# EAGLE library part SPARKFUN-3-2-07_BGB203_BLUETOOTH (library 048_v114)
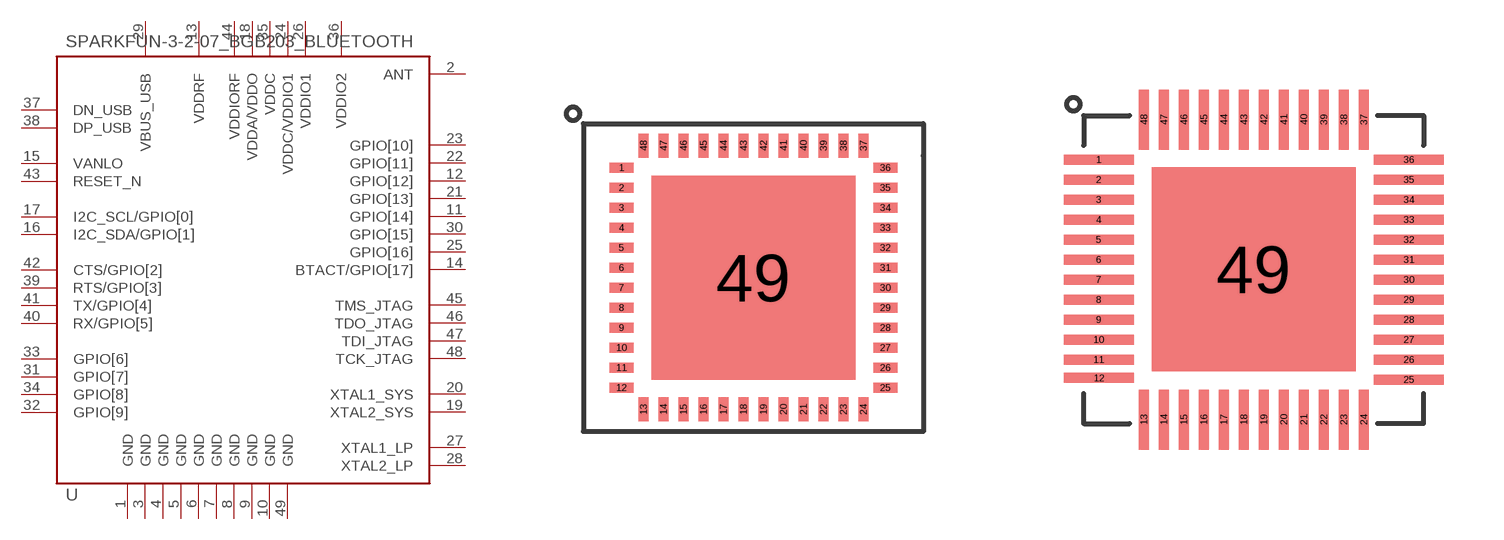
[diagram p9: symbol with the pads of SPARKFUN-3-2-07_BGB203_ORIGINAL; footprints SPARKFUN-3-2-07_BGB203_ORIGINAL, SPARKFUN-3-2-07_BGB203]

Designator prefix -

## SPARKFUN-3-2-07_BGB203_BLUETOOTHOLD  [SPARKFUN-3-2-07_BGB203_ORIGINAL]
1  GND
2  ANT
3  GND
4  GND
5  GND
6  GND
7  GND
8  GND
9  GND
10  GND
11  GPIO[14]
12  GPIO[12]
13  VDDRF
14  BTACT/GPIO[17]
15  VANLO
16  I2C_SDA/GPIO[1]
17  I2C_SCL/GPIO[0]
18  VDDA/VDDO
19  XTAL2_SYS
20  XTAL1_SYS
21  GPIO[13]
22  GPIO[11]
23  GPIO[10]
24  VDDC/VDDIO1
25  GPIO[16]
26  VDDIO1
27  XTAL1_LP
28  XTAL2_LP
29  VBUS_USB
30  GPIO[15]
31  GPIO[7]
32  GPIO[9]
33  GPIO[6]
34  GPIO[8]
35  VDDC
36  VDDIO2
37  DN_USB
38  DP_USB
39  RTS/GPIO[3]
40  RX/GPIO[5]
41  TX/GPIO[4]
42  CTS/GPIO[2]
43  RESET_N
44  VDDIORF
45  TMS_JTAG
46  TDO_JTAG
47  TDI_JTAG
48  TCK_JTAG
49  GND

## SPARKFUN-3-2-07_BGB203_BLUETOOTHSMD  [SPARKFUN-3-2-07_BGB203]
Pads as for SPARKFUN-3-2-07_BGB203_ORIGINAL

## Footprint SPARKFUN-3-2-07_BGB203_ORIGINAL (pad centres in mm)
smd 0.6 x 0.25: 1 0,0; 2 0,-0.5; 3 0,-1; 4 0,-1.5; 5 0,-2; 6 0,-2.5; 7 0,-3; 8 0,-3.5; 9 0,-4; 10 0,-4.5; 11 0,-5; 12 0,-5.5; 25 6.6,-5.5; 26 6.6,-5; 27 6.6,-4.5; 28 6.6,-4; 29 6.6,-3.5; 30 6.6,-3; 31 6.6,-2.5; 32 6.6,-2; 33 6.6,-1.5; 34 6.6,-1; 35 6.6,-0.5; 36 6.6,0
smd 0.25 x 0.6: 13 0.55,-6.045; 14 1.05,-6.045; 15 1.55,-6.045; 16 2.05,-6.045; 17 2.55,-6.045; 18 3.05,-6.045; 19 3.55,-6.045; 20 4.05,-6.045; 21 4.55,-6.045; 22 5.05,-6.045; 23 5.55,-6.045; 24 6.05,-6.045; 37 6.05,0.55; 38 5.55,0.55; 39 5.05,0.55; 40 4.55,0.55; 41 4.05,0.55; 42 3.55,0.55; 43 3.05,0.55; 44 2.55,0.55; 45 2.05,0.55; 46 1.55,0.55; 47 1.05,0.55; 48 0.55,0.55
smd 5.1 x 5.1: 49 3.3,-2.75

## Footprint SPARKFUN-3-2-07_BGB203 (pad centres in mm)
smd 1.75 x 0.25: 1 -3.88,2.75; 2 -3.88,2.25; 3 -3.88,1.75; 4 -3.88,1.25; 5 -3.88,0.75; 6 -3.88,0.25; 7 -3.88,-0.25; 8 -3.88,-0.75; 9 -3.88,-1.25; 10 -3.88,-1.75; 11 -3.88,-2.25; 12 -3.87,-2.71; 25 3.88,-2.75; 26 3.88,-2.25; 27 3.88,-1.75; 28 3.88,-1.25; 29 3.88,-0.75; 30 3.88,-0.25; 31 3.88,0.25; 32 3.88,0.75; 33 3.88,1.25; 34 3.88,1.75; 35 3.88,2.25; 36 3.88,2.75
smd 0.25 x 1.5: 13 -2.75,-3.75; 14 -2.25,-3.75; 15 -1.75,-3.75; 16 -1.25,-3.75; 17 -0.75,-3.75; 18 -0.25,-3.75; 19 0.25,-3.75; 20 0.75,-3.75; 21 1.25,-3.75; 22 1.75,-3.75; 23 2.25,-3.75; 24 2.75,-3.75; 37 2.75,3.75; 38 2.25,3.75; 39 1.75,3.75; 40 1.25,3.75; 41 0.75,3.75; 42 0.25,3.75; 43 -0.25,3.75; 44 -0.75,3.75; 45 -1.25,3.75; 46 -1.75,3.75; 47 -2.25,3.75; 48 -2.75,3.75
smd 5.1 x 5.1: 49 -0.002,0.007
